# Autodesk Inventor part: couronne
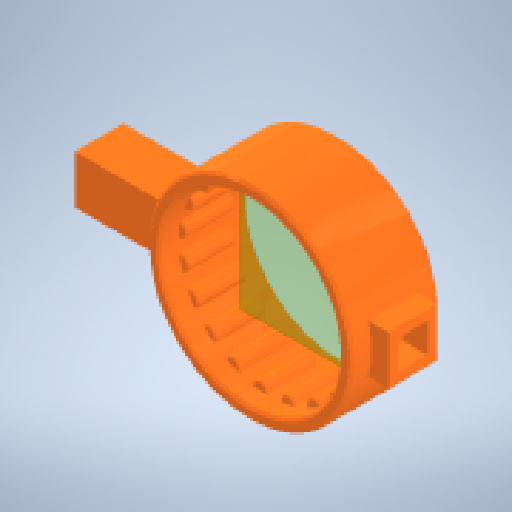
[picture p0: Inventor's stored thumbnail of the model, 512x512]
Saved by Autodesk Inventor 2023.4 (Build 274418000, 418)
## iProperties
Created: 2025-06
Part Number: couronne
Material: Plastique ABS
Document SubType Name: Modeling
Designer: mel
Density: 1.06 g/cm^3
Appearance: Lisse - Blanc
Mass: 8.63314 g
Surface Area: 66.1651 cm^2
Volume: 8.14447 cm^3
Author: mel
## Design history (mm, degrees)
feature "Housing"
node "Plan de construction3"
sketch "Esquisse1"
  geometry: L1 (40, 5)-(19, 5); L2 (19, 5)-(19, -5); L3 (19, -5)-(40, -5); L4 (40, -5)-(40, 5); C1 r 21 at (0, 0) reference; 3 further points
  constraints: 8 end point, 2 parallel, 1 horizontal, 1 perpendicular
  dimensions: "d1" = 19 distance from line of L2 C1.centre; "d2" = 40 distance from line of L4 C1.centre; "d3" = 5 distance from line of L1 C1.centre; "d4" = 5 distance from line of C1.centre L3 (= d3)
extrude "Extrusion1" join sketch "Esquisse1" stored distance "d5" = 10 (= 2 x d3); taper "d6" = 0 deg
sketch "Esquisse2"
  geometry: L1 (0, 10)-(10, 10) reference; L2 (0, 0)-(0, 10) reference; L3 (10, 0)-(0, 0) reference; L4 (10, 10)-(10, 0) reference; L5 (2, 8)-(8, 8); L6 (8, 8)-(8, 2); L7 (8, 2)-(2, 2); L8 (2, 2)-(2, 8); 1 further point
  constraints: 8 end point, 3 other
extrude "Extrusion2" cut sketch "Esquisse2" distance "d8" = 10 (= 2 x d3); taper "d9" = 0 deg
node "Plan de construction2"
sketch "Esquisse3"
  geometry: L1 (-19.556, 5)-(-24.556, 5); L2 (-24.556, 5)-(-24.556, -5); L3 (-24.556, -5)-(-19.556, -5); L4 (-19.556, -5)-(-19.556, 5) reference; C1 r 21 at (0, 0) reference; 3 further points
  constraints: 8 end point, 2 parallel, 1 horizontal, 1 perpendicular, 1 vertical
  dimensions: "d10" = 5 distance between parallel lines of L2 L4; "d11" = 19.55601 distance from line of C1.centre L4 (derived)
extrude "Extrusion3" join sketch "Esquisse3" stored distance "d12" = 10; taper "d13" = 0 deg
sketch "Esquisse4"
  geometry: L1 (0, 0)-(-10, 0) reference; L2 (0, 10)-(0, 0) reference; L3 (-10, 10)-(0, 10) reference; L4 (-10, 0)-(-10, 10) reference; L5 (-2, 2)-(-8, 2); L6 (-8, 2)-(-8, 8); L7 (-8, 8)-(-2, 8); L8 (-2, 8)-(-2, 2); 1 further point
  constraints: 8 end point, 3 other
extrude "Extrusion4" cut sketch "Esquisse4" distance "d14" = 5; taper "d15" = 0 deg
node "Solide1"
node "Boucle projetée1"
node "Boucle projetée2"
